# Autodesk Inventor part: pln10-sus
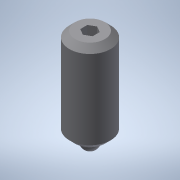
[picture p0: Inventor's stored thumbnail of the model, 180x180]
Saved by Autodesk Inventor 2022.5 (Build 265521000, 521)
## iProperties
Created: 2016-12
Part Number: pln10-sus
Material: 一般
Document SubType Name: Modeling
Designer: imaocorp
Density: 1 g/cm^3
Appearance: 既定
Author: imaocorp
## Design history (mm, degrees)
node "pln10-sus.x_t1"
node "pln10-sus"
node "Base1"
